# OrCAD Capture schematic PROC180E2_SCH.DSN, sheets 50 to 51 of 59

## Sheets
50 20. CPLD CLOCK GENERATION: size C; title: CPLD CLOCK GENERATION
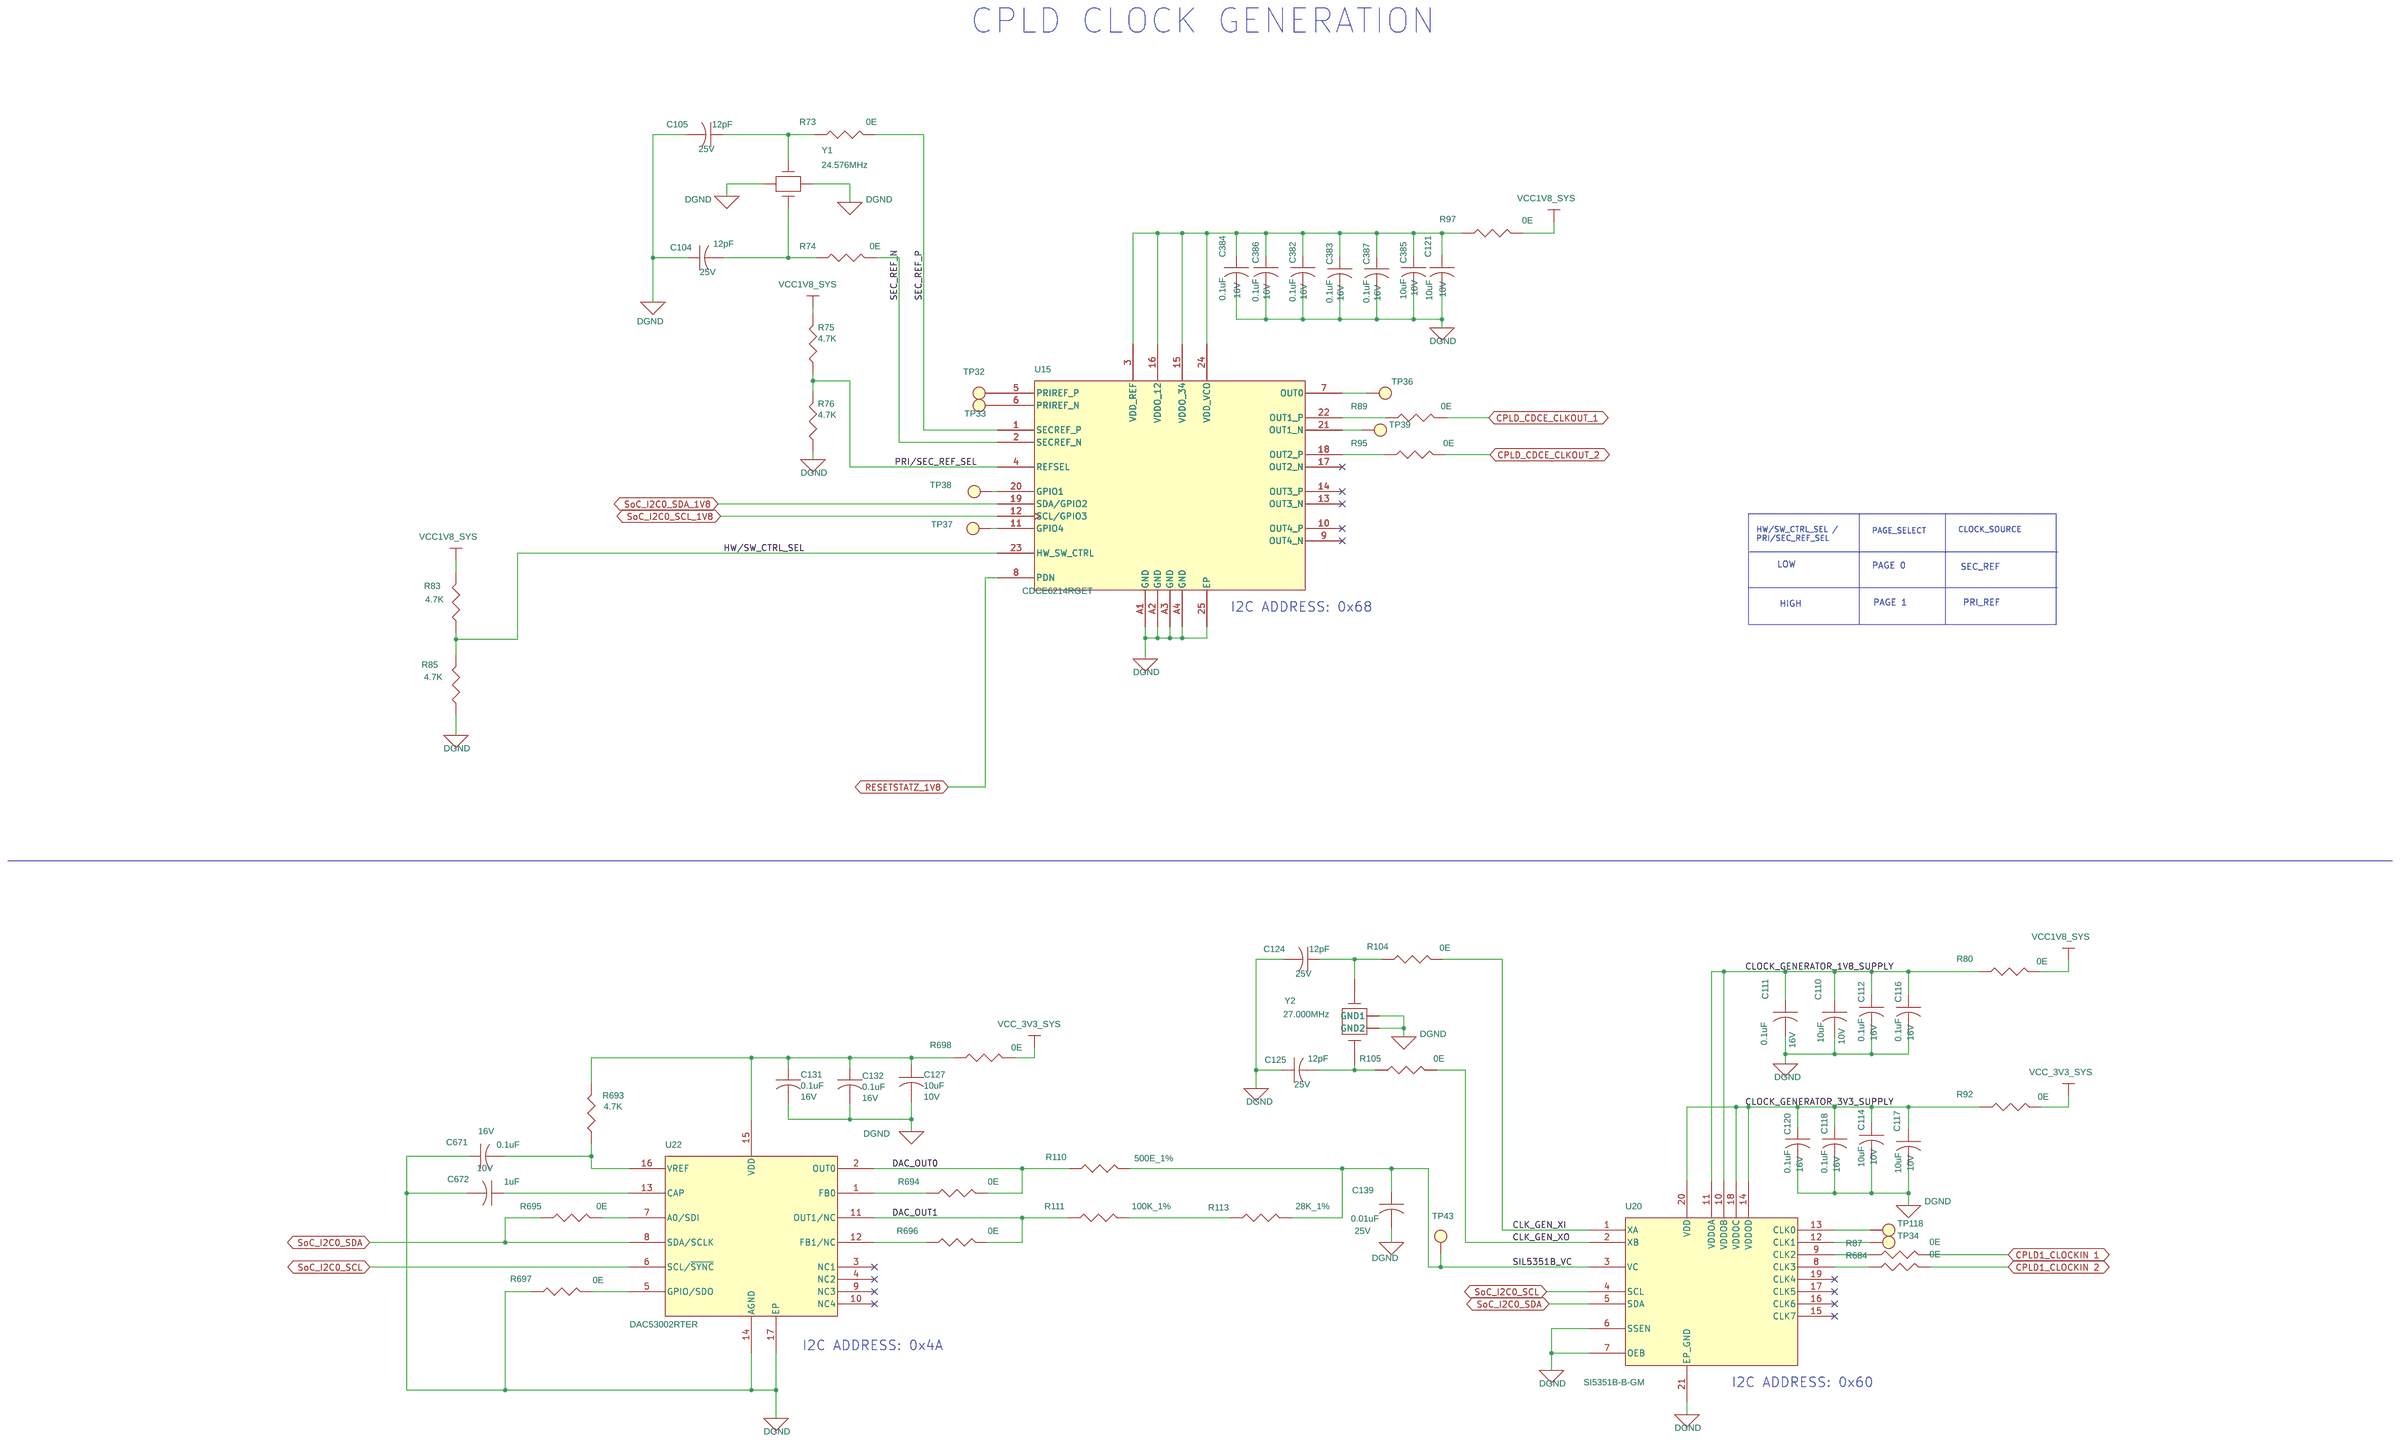
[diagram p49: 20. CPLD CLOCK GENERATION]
51 35. USB1 TYPE-A: size C; title: USB1 TYPE-A
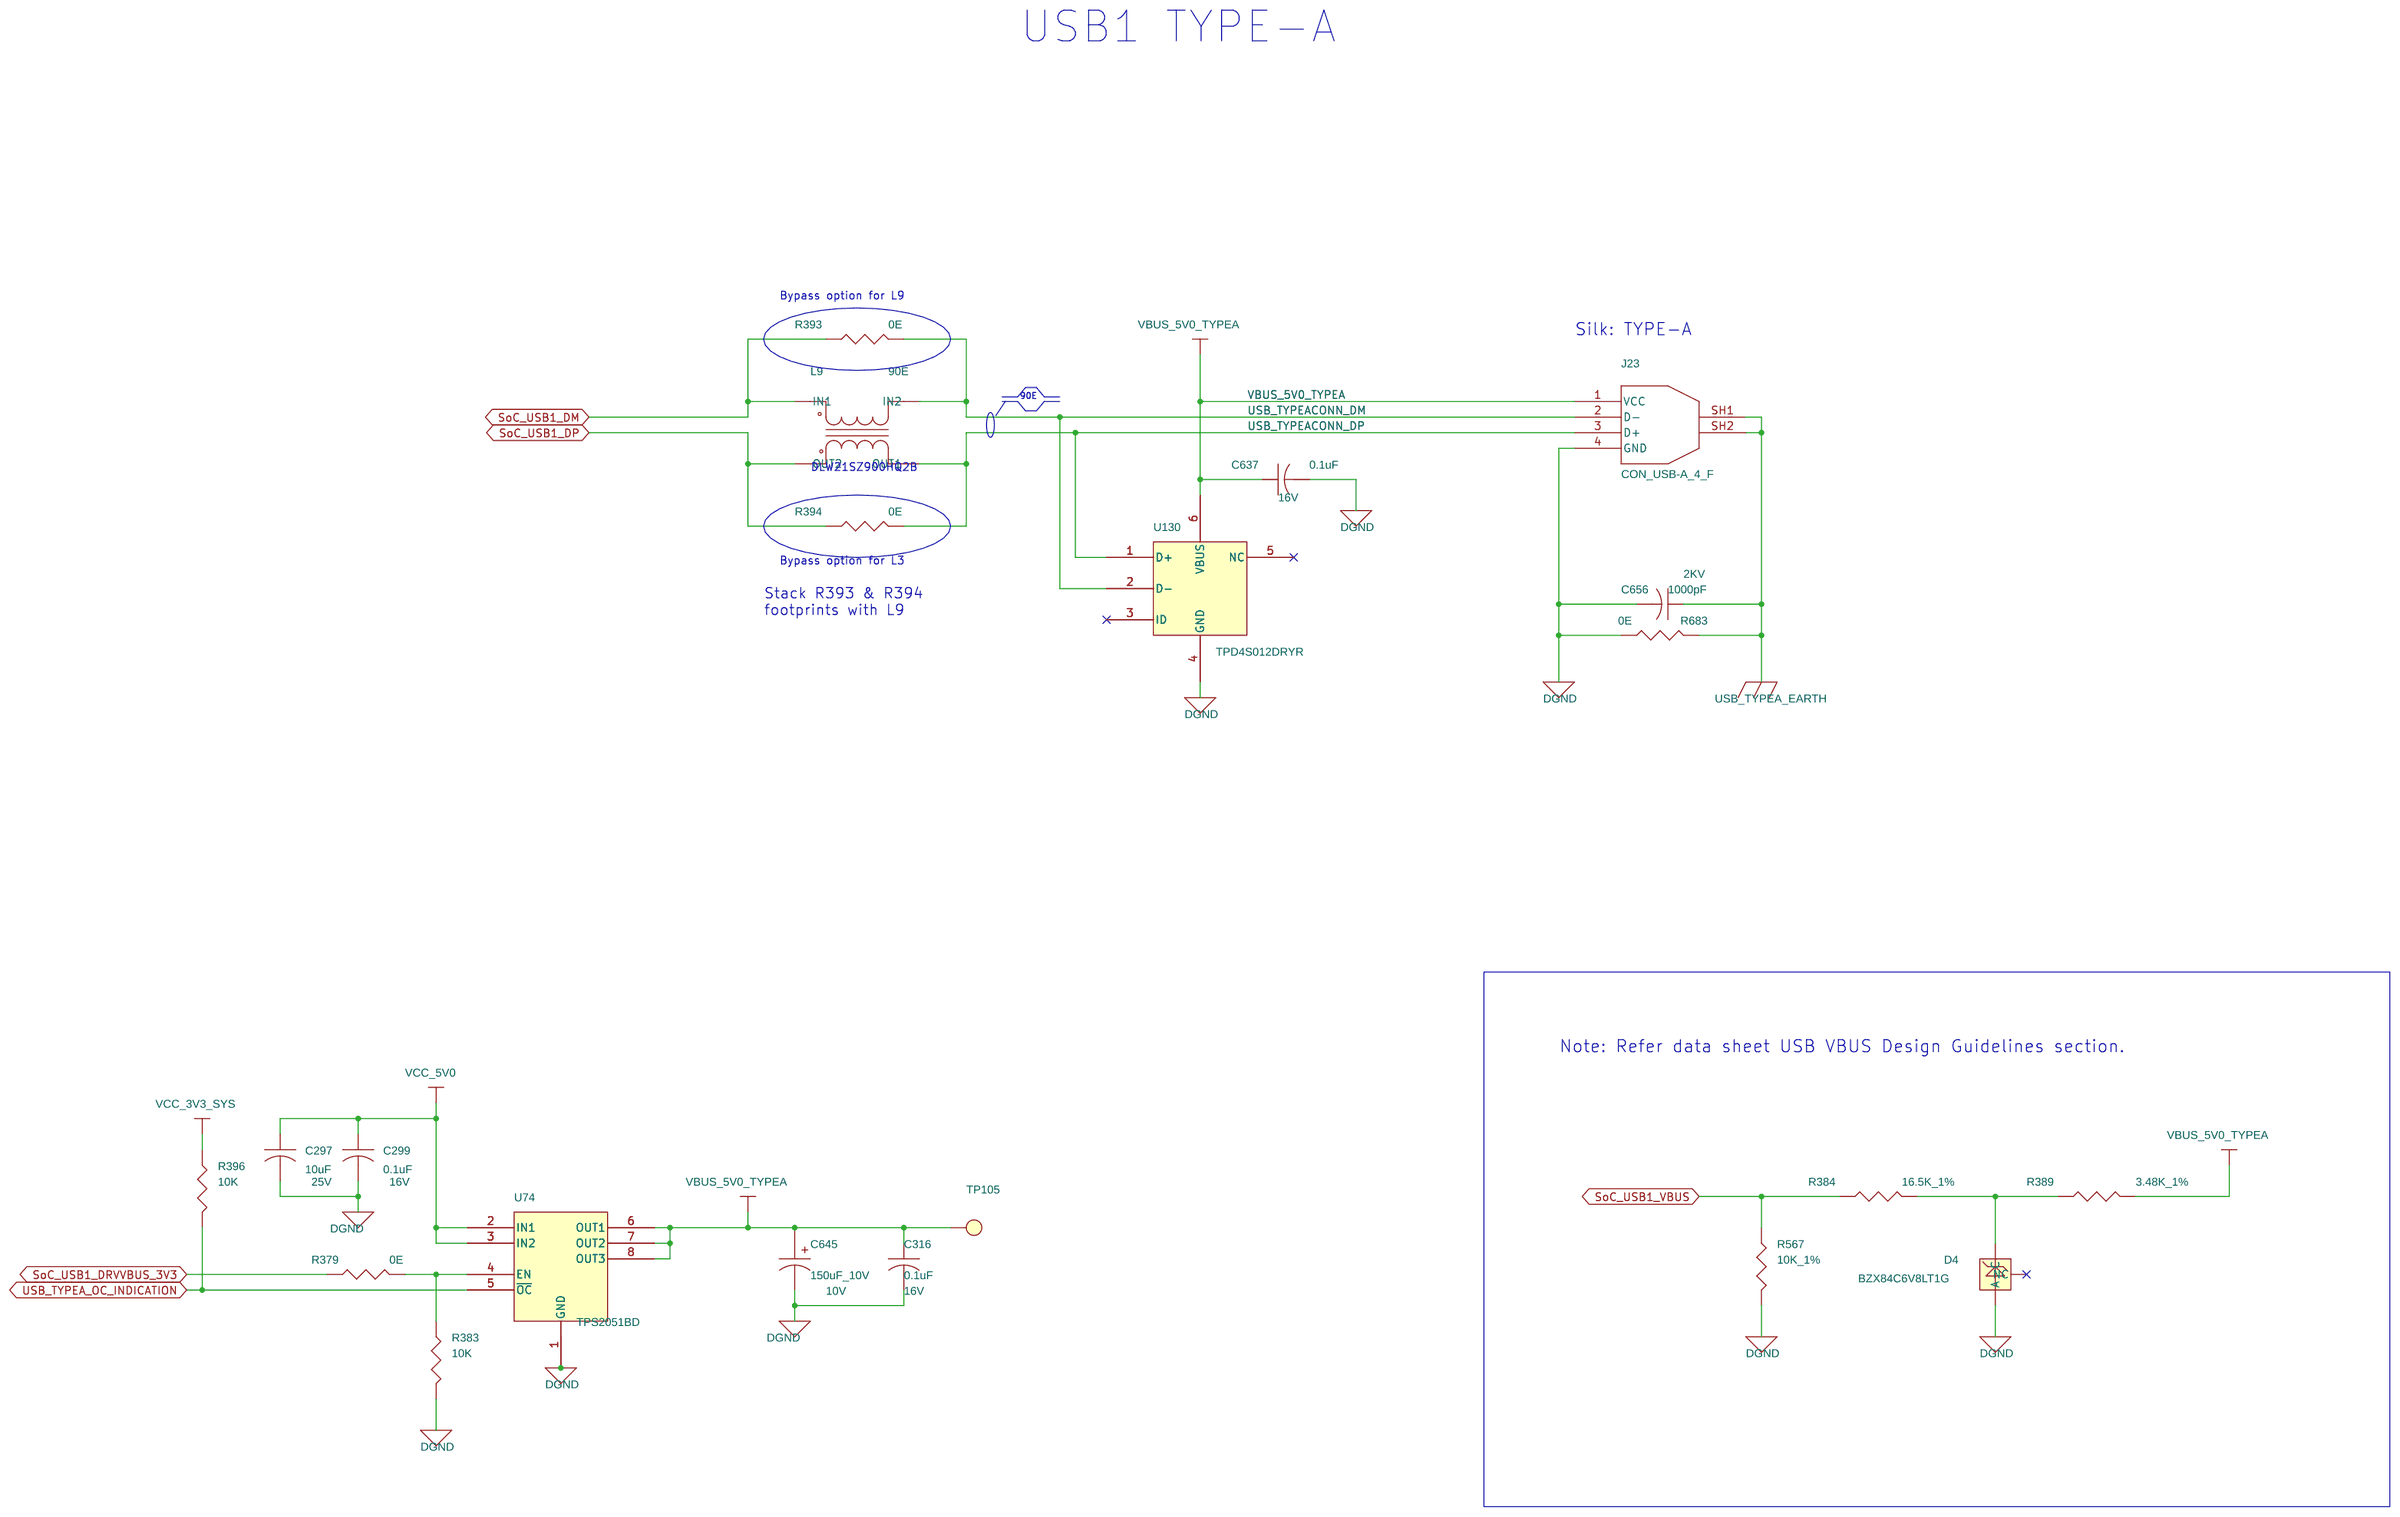
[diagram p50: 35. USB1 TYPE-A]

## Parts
sheet 20. CPLD CLOCK GENERATION
C104  12pF  [CAP0201_0-5]
C105  12pF  [CAP0201_0-5]
C110  10uF  [CAP0402_0-75]
C111  0.1uF  [CAP0201_0-5]
C112  0.1uF  [CAP0201_0-5]
C114  10uF  [CAP0402_0-75]
C116  0.1uF  [CAP0201_0-5]
C117  10uF  [CAP0402_0-75]
C118  0.1uF  [CAP0201_0-5]
C120  0.1uF  [CAP0201_0-5]
C121  10uF  [CAP0402_0-75]
C124  12pF  [CAP0201_0-5]
C125  12pF  [CAP0201_0-5]
C127  10uF  [CAP0402_0-75]
C131  0.1uF  [CAP0201_0-5]
C132  0.1uF  [CAP0201_0-5]
C139  0.01uF  [CAP0201_0-5]
C382  0.1uF  [CAP0201_0-5]
C383  0.1uF  [CAP0201_0-5]
C384  0.1uF  [CAP0201_0-5]
C385  10uF  [CAP0402_0-75]
C386  0.1uF  [CAP0201_0-5]
C387  0.1uF  [CAP0201_0-5]
C671  0.1uF  [CAP0201_0-5]
C672  1uF  [CAP0201_0-5]
R73  0E  [RES0201_0-5]
R74  0E  [RES0201_0-5]
R75  4.7K  [RES0201_0-5]
R76  4.7K  [RES0201_0-5]
R80  0E  [RES0603_0-75]
R83  4.7K  [RES0201_0-5]
R85  4.7K  [RES0201_0-5]
R87  0E  [RES0201_0-5]
R89  0E  [RES0201_0-5]
R92  0E  [RES0603_0-75]
R95  0E  [RES0201_0-5]
R97  0E  [RES0603_0-75]
R104  0E  [RES0201_0-5]
R105  0E  [RES0201_0-5]
R110  500E_1%  [RES0402_0-5]
R111  100K_1%  [RES0402_0-5]
R113  28K_1%  [RES0402_0-5]
R684  0E  [RES0201_0-5]
R693  4.7K  [RES0201_0-5]
R694  0E  [RES0201_0-5]
R695  0E  [RES0201_0-5]
R696  0E  [RES0201_0-5]
R697  0E  [RES0201_0-5]
R698  0E  [RES0603_0-75]
TP32  TP30_SMD  [TP30_SMD]
TP33  TP30_SMD  [TP30_SMD]
TP34  TP30_SMD  [TP30_SMD]
TP36  TP30_SMD  [TP30_SMD]
TP37  TP30_SMD  [TP30_SMD]
TP38  TP30_SMD  [TP30_SMD]
TP39  TP30_SMD  [TP30_SMD]
TP43  TP30_SMD  [TP30_SMD]
TP118  TP30_SMD  [TP30_SMD]
U15  CDCE6214RGET  [WFQFN24_CDCE6214-Q1_160X160_0-9]
U20  SI5351B-B-GM  [QFN20_19-68_160X160_0-9_EP2-7]
U22  DAC53002RTER  [WQFN16_19-68_120X120_0-8_EP1-7]
Y1  24.576MHz  [XTAL4_ABMM_280X200_SMD_1-3]
Y2  27.000MHz  [XTAL4_ABM8_130X110_0-8_SMD]
sheet 35. USB1 TYPE-A
C297  10uF  [CAP0603_1]
C299  0.1uF  [CAP0201_0-5]
C316  0.1uF  [CAP0201_0-5]
C637  0.1uF  [CAP0201_0-5]
C645  150uF_10V  [CAPT7343D_3-25]
C656  1000pF  [CAP1206_1-75]
D4  BZX84C6V8LT1G  [SOT23-123_1-2]
J23  CON_USB-A_4_F  [CON_USBA4_629104151_S_R_S_7-4]
L9  90E  [IND4_DLW21H_90X60_SMD_1-4]
R379  0E  [RES0201_0-5]
R383  10K  [RES0201_0-5]
R384  16.5K_1%  [RES0402_0-5]
R389  3.48K_1%  [RES0201_0-5]
R393  0E  [RES0402_0-5]
R394  0E  [RES0402_0-5]
R396  10K  [RES0201_0-5]
R567  10K_1%  [RES0201_0-5]
R683  0E  [RES0603_0-75]
TP105  TP20_SMD  [TP20_SMD]
U74  TPS2051BD  [SOIC8_1-8]
U130  TPD4S012DRYR  [SON6_SN74LVC2G17_40X60_0-6]

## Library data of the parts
C104 C105 C124 C125 = CAP: CAP CERAMIC 12pF 25V 5% C0G(NP0) AUTO 0201; Chkd/date: MANIRAJA/311221; Crtd /date: ALVY/301221; Custom_Duty: 15%; Customs_HS_Code: 85322990; Distributor_name: MOUSER; Distributor_part_number: 81-GRT0335C1E120JA2D; Footprint Path: Y:\MIS_DATABASE\Library\ALTIUM_TOOL\PCB_FOOTPRINTS\Altium_Footprint_Lib.PcbLib; Height: 0.33MM; Library Path: Y:\MIS_DATABASE\Library\ALTIUM_TOOL\SCHEMATICS_PARTS\MS_DISCRETE_Library.schlib; Mfr_name: MURATA; Mfr_part_number: GRT0335C1E120JA02D; Mistral Part No: 120021120012-R; Package: 0201; Part_type: CAPACITORS\CERAMIC; Project: AM62Q_SKEVM_BRD; RoHS: RoHS; Temperature: -55°C+125°C; Tolerance: 5%; Voltage: 25V; Wattage: NA; Weight: 0.33mg; Datasheet: Y:\MIS_DATABASE\DATASHEETS\CAPACITORS\GRT0335C1E120JA02.PDF
C110 C114 C117 C121 C127 C385 = CAP: CAP CERAMIC 10uF 10V 20% X5R 0402; Chkd/date: PRADEEP/130623; Crtd /date: PRADEEP/130623; Custom_Duty: 15%; Customs_HS_Code: 85322990; Distributor_name: NA; Distributor_part_number: NA; Footprint Path: Y:\MIS_DATABASE\Library\ALTIUM_TOOL\PCB_FOOTPRINTS\Altium_Footprint_Lib.PcbLib; Height: 0.55MM; Library Path: Y:\MIS_DATABASE\Library\ALTIUM_TOOL\SCHEMATICS_PARTS\MS_DISCRETE_Library.schlib; Mfr_name: MURATA; Mfr_part_number: GRM155R61A106ME18; Mistral Part No: 120022060018-R; Package: 0402; Part_type: CAPACITORS\CERAMIC; Project: AM62P_SK; RoHS: RoHS; Temperature: -55°C+85°C; Tolerance: 20%; Voltage: 10V; Wattage: NA; Weight: 6mg; Datasheet: Y:\MIS_DATABASE\DATASHEETS\CAPACITORS\MURATA-GXX-SER_NOV17.PDF
C111 C112 C116 C118 C120 C131 C132 C299 C316 C382-C384 C386 C387 C637 C671 = CAP: CAP CERAMIC 0.1uF 16V 10% X7S AUTO 0201; Chkd/date: MANIRAJA/110321; Crtd /date: ALVY/110321; Custom_Duty: 15%; Customs_HS_Code: 85322990; Distributor_name: DIGIKEY; Distributor_part_number: 490-GRT033C71C104KE01DTR-ND; Footprint Path: Y:\MIS_DATABASE\Library\ALTIUM_TOOL\PCB_FOOTPRINTS\Altium_Footprint_Lib.PcbLib; Height: 0.33MM; Library Path: Y:\MIS_DATABASE\Library\ALTIUM_TOOL\SCHEMATICS_PARTS\MS_DISCRETE_Library.schlib; Mfr_name: MURATA; Mfr_part_number: GRT033C71C104KE01D; Mistral Part No: 120021030007-R; Package: 0201; Part_type: CAPACITORS\CERAMIC; Project: J7ES_SK_BRD; RoHS: RoHS; Temperature: -55°C+125°C; Tolerance: 10%; Voltage: 16V; Wattage: NA; Weight: 330mg; Datasheet: Y:\MIS_DATABASE\DATASHEETS\CAPACITORS\GRT033C71C104KE01.PDF
C139 = CAP: CAP CERAMIC 0.01uF 25V 10% X5R AUTO 0201; Chkd/date: MANIRAJA/311221; Crtd /date: ALVY/301221; Custom_Duty: 15%; Customs_HS_Code: 85322990; Distributor_name: MOUSER; Distributor_part_number: 81-GRT033R61E103KE1D; Footprint Path: Y:\MIS_DATABASE\Library\ALTIUM_TOOL\PCB_FOOTPRINTS\Altium_Footprint_Lib.PcbLib; Height: 0.33MM; Library Path: Y:\MIS_DATABASE\Library\ALTIUM_TOOL\SCHEMATICS_PARTS\MS_DISCRETE_Library.schlib; Mfr_name: MURATA; Mfr_part_number: GRT033R61E103KE01D; Mistral Part No: 120021120019-R; Package: 0201; Part_type: CAPACITORS\CERAMIC; Project: AM62Q_SKEVM_BRD; RoHS: RoHS; Temperature: -55°C+85°C; Tolerance: 10%; Voltage: 25V; Wattage: NA; Weight: 0.33mg; Datasheet: Y:\MIS_DATABASE\DATASHEETS\CAPACITORS\GRT033R61E103KE01.PDF
C672 = CAP: CAP CERAMIC 1uF 10V 20% X6S 0201; Chkd/date: PRADEEP/130623; Crtd /date: PRADEEP/130623; Custom_Duty: 15%; Customs_HS_Code: 85322990; Distributor_name: DIGIKEY; Distributor_part_number: 490-GRT033C81A105ME13DTR-ND; Footprint Path: Y:\MIS_DATABASE\Library\ALTIUM_TOOL\PCB_FOOTPRINTS\Altium_Footprint_Lib.PcbLib; Height: 0.39MM; Library Path: Y:\MIS_DATABASE\Library\ALTIUM_TOOL\SCHEMATICS_PARTS\MS_DISCRETE_Library.schlib; Mfr_name: MURATA; Mfr_part_number: GRT033C81A105ME13D; Mistral Part No: 120022060020-R; Package: 0201; Part_type: CAPACITORS\CERAMIC; Project: AM62P_SK; RoHS: RoHS; Temperature: -55°C+105°C; Tolerance: 20%; Voltage: 10V; Wattage: NA; Weight: NA; Datasheet: Y:\MIS_DATABASE\DATASHEETS\CAPACITORS\GRT033C81A105ME13D.PDF
R73 R74 R87 R89 R95 R104 R105 R684 = RESISTOR: RES 0E 1/20W 5% 0201; Chkd/date: NAVEED/301214; Crtd /date: MUDDU/120710; Custom_Duty: 15%; Customs_HS_Code: 85332119; Distributor_name: DIGIKEY; Distributor_part_number: 311-0.0NCT-ND; Footprint Path: Y:\MIS_DATABASE\Library\ALTIUM_TOOL\PCB_FOOTPRINTS\Altium_Footprint_Lib.PcbLib; Height: 0.26MM; Library Path: Y:\MIS_DATABASE\Library\ALTIUM_TOOL\SCHEMATICS_PARTS\MS_DISCRETE_Library.schlib; Mfr_name: YAGEO AMERICA; Mfr_part_number: RC0201JR-070RL; Mistral Part No: 110010070067-R; Package: 0201; Part_type: RESISTORS\FIXED; Project: PB_BUGBASE; RoHS: RoHS; SIGNAL_MODEL: RESISTOR_RES0201_0-5_22E_1%_22E_1%; Temperature: -55°C+125°C; Tolerance: 5%; Voltage: NA; Wattage: 1/20W; Weight: 0.17mg; Datasheet: Y:\MIS_DATABASE\DATASHEETS\RESISTORS\RCXXXXL-SER_MAR18.PDF
R75 R76 R83 R85 R693 = RESISTOR: RES 4.7K 1/20W 5% 0201; Chkd/date: MANIRAJA/200921; Crtd /date: ALVY/200921; Custom_Duty: 15%; Customs_HS_Code: 85332119; Distributor_name: DIGIKEY; Distributor_part_number: 311-4.7KNCT-ND; Footprint Path: Y:\MIS_DATABASE\Library\ALTIUM_TOOL\PCB_FOOTPRINTS\Altium_Footprint_Lib.PcbLib; Height: 0.26MM; Library Path: Y:\MIS_DATABASE\Library\ALTIUM_TOOL\SCHEMATICS_PARTS\MS_DISCRETE_Library.schlib; Mfr_name: YAGEO AMERICA; Mfr_part_number: RC0201JR-074K7L; Mistral Part No: 110021090007-R; Package: 0201; Part_type: RESISTORS\FIXED; Project: TI_AM62x SKEVM_BRD; RoHS: RoHS; Temperature: -55°C+125°C; Tolerance: 5%; Voltage: NA; Wattage: 1/20W; Weight: 0.17mg; Datasheet: Y:\MIS_DATABASE\DATASHEETS\RESISTORS\RCXXXXL-SER_MAR18.PDF
R80 R92 R97 R698 = RESISTOR: RES 0E 1/10W 5% 0603; Chkd/date: MANIRAJA/051217; Crtd /date: BAVISH/180211; Custom_Duty: 15%; Customs_HS_Code: 85332119; Distributor_name: DIGIKEY; Distributor_part_number: 311-0.0GRCT-ND; Footprint Path: Y:\MIS_DATABASE\Library\ALTIUM_TOOL\PCB_FOOTPRINTS\Altium_Footprint_Lib.PcbLib; Height: 0.55MM; Library Path: Y:\MIS_DATABASE\Library\ALTIUM_TOOL\SCHEMATICS_PARTS\MS_DISCRETE_Library.schlib; Mfr_name: YAGEO AMERICA; Mfr_part_number: RC0603JR-070RL; Mistral Part No: 110011020013-R; Package: 0603; Part_type: RESISTORS\FIXED; Project: KENNEL; RoHS: RoHS; Temperature: -55°C+155°C; Tolerance: 5%; Voltage: NA; Wattage: 1/10W; Weight: 2mg; Datasheet: Y:\MIS_DATABASE\DATASHEETS\RESISTORS\RCXXXXL-SER_MAR18.PDF
R110 = RESISTOR: RES 500E 1/16W 1% 0402; Crtd /date: TAMILARASU/080224; Custom_Duty: 15%; Customs_HS_Code: 85332119; Distributor_name: DIGIKEY; Distributor_part_number: 13-RT0402FRE07500RLCT-ND; Footprint Path: Y:\MIS_DATABASE\Library\ALTIUM_TOOL\PCB_FOOTPRINTS\Altium_Footprint_Lib.PcbLib; Height: 0.35MM; Library Path: Y:\MIS_DATABASE\Library\ALTIUM_TOOL\SCHEMATICS_PARTS\MS_DISCRETE_Library.schlib; Mfr_name: YAGEO AMERICA; Mfr_part_number: RT0402FRE07500RL; Mistral Part No: 110024020024-R; Package: 0402; Part_type: RESISTORS\FIXED; Project: AM62D_EVM; RoHS: RoHS; Temperature: -55°C+155°C; Tolerance: 1%; Voltage: NA; Wattage: 1/16W; Weight: 0.65mg; Datasheet: Y:\MIS_DATABASE\DATASHEETS\RESISTORS\YAGEO_RT-SERIES.PDF
R111 = RESISTOR: RES 100K 1/10W 1% 0402; Chkd/date: VASANTHA/201216; Crtd /date: MAZHAR/130306; Custom_Duty: 15%; Customs_HS_Code: 85332119; Distributor_name: DIGIKEY; Distributor_part_number: P100KLCT-ND; Footprint Path: Y:\MIS_DATABASE\Library\ALTIUM_TOOL\PCB_FOOTPRINTS\Altium_Footprint_Lib.PcbLib; Height: 0.40MM; Library Path: Y:\MIS_DATABASE\Library\ALTIUM_TOOL\SCHEMATICS_PARTS\MS_DISCRETE_Library.schlib; Mfr_name: PANASONIC-ECG; Mfr_part_number: ERJ-2RKF1003X; Mistral Part No: 110009030187-R; Package: 0402; Part_type: RESISTORS\FIXED; Project: J32; RoHS: RoHS; Temperature: -55°C+155°C; Tolerance: 1%; Voltage: NA; Wattage: 1/10W; Weight: 0.8mg; Datasheet: Y:\MIS_DATABASE\DATASHEETS\RESISTORS\PAN-ERJSER_NOV17.PDF
R113 = RESISTOR: RES 28K 1/10W 1% 0402; Chkd/date: MAZHAR/250809; Crtd /date: USMAN/120809; Custom_Duty: 15%; Customs_HS_Code: 85332119; Distributor_name: DIGIKEY; Distributor_part_number: P28.0KLCT-ND; Footprint Path: Y:\MIS_DATABASE\Library\ALTIUM_TOOL\PCB_FOOTPRINTS\Altium_Footprint_Lib.PcbLib; Height: 0.40MM; Library Path: Y:\MIS_DATABASE\Library\ALTIUM_TOOL\SCHEMATICS_PARTS\MS_DISCRETE_Library.schlib; Mfr_name: PANASONIC-ECG; Mfr_part_number: ERJ-2RKF2802X; Mistral Part No: 110009080014-R; Package: 0402; Part_type: RESISTORS\FIXED; Project: VMEFMCD; RoHS: RoHS; Temperature: -55°C+155°C; Tolerance: 1%; Voltage: NA; Wattage: 1/10W; Weight: 0.8mg; Datasheet: Y:\MIS_DATABASE\DATASHEETS\RESISTORS\PAN-ERJSER_NOV17.PDF
R379 R694-R697 = RESISTOR: RES 0E 1/20W 5% 0201; Chkd/date: NAVEED/301214; Crtd /date: MUDDU/120710; Custom_Duty: 15%; Customs_HS_Code: 85332119; Distributor_name: DIGIKEY; Distributor_part_number: 311-0.0NCT-ND; Footprint Path: Y:\MIS_DATABASE\Library\ALTIUM_TOOL\PCB_FOOTPRINTS\Altium_Footprint_Lib.PcbLib; Height: 0.26MM; Library Path: Y:\MIS_DATABASE\Library\ALTIUM_TOOL\SCHEMATICS_PARTS\MS_DISCRETE_Library.schlib; Mfr_name: YAGEO AMERICA; Mfr_part_number: RC0201JR-070RL; Mistral Part No: 110010070067-R; Package: 0201; Part_type: RESISTORS\FIXED; Project: PB_BUGBASE; RoHS: RoHS; Temperature: -55°C+125°C; Tolerance: 5%; Voltage: NA; Wattage: 1/20W; Weight: 0.17mg; Datasheet: Y:\MIS_DATABASE\DATASHEETS\RESISTORS\RCXXXXL-SER_MAR18.PDF
TP32-TP34 TP36-TP39 TP43 TP118 = TESTPOINT: TESTPOINT CIR 30 SMD; Chkd/date: SHREESHAIL/171006; Crtd /date: MAZHAR/171006; Custom_Duty: NA; Customs_HS_Code: NA; Distributor_name: NA; Distributor_part_number: NA; Footprint Path: Y:\MIS_DATABASE\Library\ALTIUM_TOOL\PCB_FOOTPRINTS\Altium_Footprint_Lib.PcbLib; Height: NA; Library Path: Y:\MIS_DATABASE\Library\ALTIUM_TOOL\SCHEMATICS_PARTS\MS_DISCRETE_Library.schlib; MECHANICAL 3D STEP FILE: NA; Mfr_name: LOCAL; Mistral Part No: 130009030930; Package: SMD; Project: BT MODULE_CSRBC04; RoHS: NA; Temperature: NA; Tolerance: NA; Voltage: NA; Wattage: NA; Weight: NA; Datasheet: NA
U15 = CDCE6214_WFQFN24: IC CLOCK GENERATOR WITH 1-PLL 4-DIFFERENTIAL O/Ps 2-I/Ps AND EEPROM WFQFN24; Chkd/date: PRADEEP/290124; Crtd /date: TAMILARASU/290124; Custom_Duty: 15%; Customs_HS_Code: 85423100; Distributor_name: DIGIKEY; Distributor_part_number: 296-CDCE6214RGETCT-ND; Footprint Path: Y:\MIS_DATABASE\Library\ALTIUM_TOOL\PCB_FOOTPRINTS\Altium_Footprint_Lib.PcbLib; Height: 0.90MM; Library Path: Y:\MIS_DATABASE\Library\ALTIUM_TOOL\SCHEMATICS_PARTS\MS_COMBINATIONAL_Library.schlib; Mfr_name: TEXAS INSTRUMENTS; Mistral Part No: 141024010005-R; Package: WFQFN24; Part_type: ICS\DIGITAL\PERIPHERAL; Project: AM62D EVM; RoHS: RoHS; Temperature: -40°C+85°C; Tolerance: NA; Voltage: NA; Wattage: NA; Weight: NA; Datasheet: Y:\MIS_DATABASE\DATASHEETS\ICS\DIGITAL\PERIPHERAL\CDCE6214.PDF
U20 = SI5351B_QFN20: IC I2C-PROGRAMMABLE ANY-FREQUENCY CMOS CLOCK GENERATOR +VCXO QFN20; Chkd/date: PRADEEP/020224; Crtd /date: TAMILARASU010224; Custom_Duty: 15%; Customs_HS_Code: 85423100; Distributor_name: DIGIKEY; Distributor_part_number: 336-2401-ND; Footprint Path: Y:\MIS_DATABASE\Library\ALTIUM_TOOL\PCB_FOOTPRINTS\Altium_Footprint_Lib.PcbLib; Height: 0.90MM; Library Path: Y:\MIS_DATABASE\Library\ALTIUM_TOOL\SCHEMATICS_PARTS\MS_COMBINATIONAL_Library.schlib; Mfr_name: SKYWORKS SOLUTIONS INC; Mistral Part No: 141024020002-R; Package: QFN20; Part_type: ICS\DIGITAL\PERIPHERAL; Project: AM62D EVM; RoHS: RoHS; Temperature: -40°C+85°C; Tolerance: NA; Voltage: NA; Wattage: NA; Weight: NA; Datasheet: Y:\MIS_DATABASE\DATASHEETS\ICS\DIGITAL\PERIPHERAL\SI5351X-B.PDF
U22 = DAC53002_WQFN16: IC 12-BIT AND 10-BIT ULTRA-LOW POWER DUAL AND SINGLE VOLTAGE AND CURRENT OUTPUT SMART DACS WQFN16; Crtd /date: SHANKARI/060924; Custom_Duty: 15%; Customs_HS_Code: 85423100; Distributor_name: DIGIKEY; Distributor_part_number: 296-DAC53002RTERCT-ND; Footprint Path: Y:\MIS_DATABASE\Library\ALTIUM_TOOL\PCB_FOOTPRINTS\Altium_Footprint_Lib.PcbLib; Height: 0.80MM; Library Path: Y:\MIS_DATABASE\Library\ALTIUM_TOOL\SCHEMATICS_PARTS\MS_ATOD_Library.schlib; Mfr_name: TEXAS INSTRUMENTS; Mistral Part No: 140224090001-R; Package: WQFN16; Part_type: ICS\DTOA; Project: AM62D_EVM; RoHS: RoHS; Temperature: -40°C+125°C; Tolerance: NA; Voltage: NA; Wattage: NA; Weight: NA; Datasheet: Y:\MIS_DATABASE\DATASHEETS\ICS\ATOD_DTOA\DAC53002RTER.PDF
Y1 = CRY4_ABMM: CRY 24.576MHz 18pF SMD; Chkd/date: MANIRAJA/040918; Crtd /date: GEETHA/040506; Custom_Duty: 24%; Customs_HS_Code: 85439000; Distributor_name: DIGIKEY; Distributor_part_number: 535-9160-1-ND; Footprint Path: Y:\MIS_DATABASE\Library\ALTIUM_TOOL\PCB_FOOTPRINTS\Altium_Footprint_Lib.PcbLib; Height: 1.30MM; Library Path: Y:\MIS_DATABASE\Library\ALTIUM_TOOL\SCHEMATICS_PARTS\MS_DISCRETE_Library.schlib; Mfr_name: ABRACON; Mfr_part_number: ABMM-24.576MHZ-B2-T; Mistral Part No: 130009030042-R; Package: SMD; Part_type: CRYSTAL; Project: SCRIPTALKMAX; RoHS: RoHS; Temperature: -20°C+70°C; Tolerance: NA; Voltage: NA; Wattage: NA; Weight: 186.03mg; Datasheet: Y:\MIS_DATABASE\DATASHEETS\MISC\CRY_OSC\ABMM-SERIES.PDF
Y2 = CRY4_ABM8: CRY 27.000MHz SMD; Chkd/date: PRADEEP/020224; Crtd /date: TAMILARASU/020224; Custom_Duty: 24%; Customs_HS_Code: 85437099; Distributor_name: DIGIKEY; Distributor_part_number: 535-9679-1-ND; Height: 0.80MM; Mfr_name: ABRACON; Mfr_part_number: ABM8-27.000MHZ-10-1-U-T; Mistral Part No: 130024020001-R; Package: SMD; Part_type: CRYSTAL; Project: AM62D EVM; RoHS: RoHS; Temperature: -10°C+60°C; Tolerance: NA; Voltage: NA; Wattage: NA; Weight: NA; Datasheet: Y:\MIS_DATABASE\DATASHEETS\MISC\CRY_OSC\ABM8-27.000MHZ-10-1-U-T.PDF
C297 = CAP: CAP CERAMIC 10uF 25V 20% X5R AUTO 0603; Chkd/date: PRADEEP/130623; Crtd /date: PRADEEP/130623; Custom_Duty: 15%; Customs_HS_Code: 85322990; Distributor_name: NA; Distributor_part_number: NA; Footprint Path: Y:\MIS_DATABASE\Library\ALTIUM_TOOL\PCB_FOOTPRINTS\Altium_Footprint_Lib.PcbLib; Height: 1.00MM; Library Path: Y:\MIS_DATABASE\Library\ALTIUM_TOOL\SCHEMATICS_PARTS\MS_DISCRETE_Library.schlib; Mfr_name: MURATA; Mfr_part_number: GRT188R61E106ME13; Mistral Part No: 120022060023-R; Package: 0603; Part_type: CAPACITORS\CERAMIC; Project: AM62P_SK; RoHS: RoHS; Temperature: -55°C+85°C; Tolerance: 20%; Voltage: 25V; Wattage: NA; Weight: 2mg; Datasheet: Y:\MIS_DATABASE\DATASHEETS\CAPACITORS\GRT188R61E106ME13.PDF
C645 = CAP_POL: CAP TANTALUM 150uF 10V 10% ESR 600mE D7343; Chkd/date: ALVY/200921; Crtd /date: MANIRAJA/200921; Custom_Duty: 15%; Customs_HS_Code: 85322990; Distributor_name: DIGIKEY; Distributor_part_number: 718-1960-1-ND; Footprint Path: Y:\MIS_DATABASE\Library\ALTIUM_TOOL\PCB_FOOTPRINTS\Altium_Footprint_Lib.PcbLib; Height: 3.10MM; Library Path: Y:\MIS_DATABASE\Library\ALTIUM_TOOL\SCHEMATICS_PARTS\MS_DISCRETE_Library.schlib; Mfr_name: VISHAY; Mfr_part_number: 293D157X9010D2TE3; Mistral Part No: 120021090007-R; Package: D7343; Part_type: CAPACITORS\TANTALUM; Project: TI_AM62x SKEVM_BRD; RoHS: RoHS; Temperature: -55°C+125°C; Tolerance: 10%; Voltage: 10V; Wattage: NA; Weight: 400mg; Datasheet: Y:\MIS_DATABASE\DATASHEETS\CAPACITORS\293D_SER_MAR20.PDF
C656 = CAP: CAP CERAMIC 1000pF 2KV 10% X7R 1206; Chkd/date: SHREESHAIL/291106; Crtd /date: MAZHAR/281106; Custom_Duty: 15%; Customs_HS_Code: 85322990; Distributor_name: DIGIKEY; Distributor_part_number: 478-2956-1-ND; Footprint Path: Y:\MIS_DATABASE\Library\ALTIUM_TOOL\PCB_FOOTPRINTS\Altium_Footprint_Lib.PcbLib; Height: 1.52MM; Library Path: Y:\MIS_DATABASE\Library\ALTIUM_TOOL\SCHEMATICS_PARTS\MS_DISCRETE_Library.schlib; Mfr_name: AVX CORPORATION; Mfr_part_number: 1206GC102KAT1A; Mistral Part No: 120015080006-R; Package: 1206; Part_type: CAPACITORS\CERAMIC; Project: ADR1B; RoHS: RoHS; Temperature: -55°C+125°C; Tolerance: 10%; Voltage: 2KV; Wattage: NA; Weight: 16.2mg; Datasheet: Y:\MIS_DATABASE\DATASHEETS\CAPACITORS\AVX_HV-MLC.PDF
D4 = DIODE_ZENER_SOT23_13: DIODE ZENER 250mW 6.8V SOT23-123; Chkd/date: MANIRAJA/031017; Crtd /date: MANIRAJA/031017; Custom_Duty: 15%; Customs_HS_Code: 85412900; Distributor_name: DIGIKEY; Distributor_part_number: BZX84C6V8LT1GOSCT-ND; Height: 1.11MM; Mfr_name: ON SEMICONDUCTOR; Mistral Part No: 130017100002-R; Package: SOT23-123; Part_type: DIODE\ZENER; Project: TI_MAXIE_CPB; RoHS: RoHS; Temperature: -65°C+150°C; Tolerance: NA; Voltage: 6.8V; Wattage: NA; Weight: 8mg; Datasheet: Y:\MIS_DATABASE\DATASHEETS\DISCRETES\DIODES\BZX84XX.PDF
J23 = CON_USB-A_4_2SH: CON USB-A TYPE 4POS FEMALE RT SMD; Chkd/date: MANIRAJA/271017; Crtd /date: MANIRAJA/271017; Custom_Duty: 24%; Customs_HS_Code: 85369090; Distributor_name: DIGIKEY; Distributor_part_number: 732-5969-1-ND; Height: 7.35MM; Manufacturer: WURTH ELECTRONICS; Mfr_name: WURTH ELECTRONICS; Mfr_part_number: 629104151021; Mistral Part No: 150017100042-R; Package: SMD; Part_type: CONNECTOR\USB; Project: TI_SVB_MAXWELL_SPM; RoHS: RoHS; Temperature: -40°C+85°C; Tolerance: NA; Voltage: NA; Wattage: NA; Weight: NA; Datasheet: Y:\MIS_DATABASE\DATASHEETS\CONNECTORS\629104151021.PDF
L9 = INDUCTOR_DLW31S: IND COMMON MODE CHOKE 90E 280mA SMD; Chkd/date: MANIRAJA/270619; Crtd /date: MANIRAJA/270619; Custom_Duty: 24%; Customs_HS_Code: 85437099; Distributor_name: NA; Distributor_part_number: NA; Footprint Path: Y:\MIS_DATABASE\Library\ALTIUM_TOOL\PCB_FOOTPRINTS\Altium_Footprint_Lib.PcbLib; Height: 1.40MM; Library Path: Y:\MIS_DATABASE\Library\ALTIUM_TOOL\SCHEMATICS_PARTS\MS_DISCRETE_Library.schlib; Mfr_name: MURATA; Mfr_part_number: DLW21SZ900HQ2B; Mistral Part No: 130019060035-R; Package: SMD; Part_type: INDUCTOR; Project: TI_J7ES_CP; RoHS: RoHS; SIGNAL_MODEL: INDUCTOR_DLW31S_IND4_DLW21H_90X_90E; Temperature: -40°C+105°C; Tolerance: NA; Voltage: NA; Wattage: NA; Weight: 11mg; Datasheet: Y:\MIS_DATABASE\DATASHEETS\DISCRETES\INDUCTORS\DLW21SZ900HQ2B.PDF
R383 R396 = RESISTOR: RES 10K 1/20W 5% 0201; Chkd/date: MANIRAJA/050517; Crtd /date: MANIRAJA/050517; Custom_Duty: 15%; Customs_HS_Code: 85332119; Distributor_name: DIGIKEY; Distributor_part_number: 311-10KNCT-ND; Footprint Path: Y:\MIS_DATABASE\Library\ALTIUM_TOOL\PCB_FOOTPRINTS\Altium_Footprint_Lib.PcbLib; Height: 0.26MM; Library Path: Y:\MIS_DATABASE\Library\ALTIUM_TOOL\SCHEMATICS_PARTS\MS_DISCRETE_Library.schlib; Mfr_name: YAGEO AMERICA; Mfr_part_number: RC0201JR-0710KL; Mistral Part No: 110010070051-R; Package: 0201; Part_type: RESISTORS\FIXED; Project: GOLDEN-I LITE; RoHS: RoHS; Temperature: -55°C+125°C; Tolerance: 5%; Voltage: NA; Wattage: 1/20W; Weight: 0.17mg; Datasheet: Y:\MIS_DATABASE\DATASHEETS\RESISTORS\RCXXXXL-SER_MAR18.PDF
R384 = RESISTOR: RES 16.5K 1/16W 1% 0402; Chkd/date: ALVY/091220; Crtd /date: MANIRAJA/091220; Custom_Duty: 15%; Customs_HS_Code: 85332119; Distributor_name: DIGIKEY; Distributor_part_number: YAG3002CT-ND; Footprint Path: Y:\MIS_DATABASE\Library\ALTIUM_TOOL\PCB_FOOTPRINTS\Altium_Footprint_Lib.PcbLib; Height: 0.40MM; Library Path: Y:\MIS_DATABASE\Library\ALTIUM_TOOL\SCHEMATICS_PARTS\MS_DISCRETE_Library.schlib; Mfr_name: YAGEO AMERICA; Mfr_part_number: RC0402FR-0716K5L; Mistral Part No: 110020120011-R; Package: 0402; Part_type: RESISTORS\FIXED; Project: TI_AM243x LP EVM; RoHS: RoHS; Temperature: -55°C+155°C; Tolerance: 1%; Voltage: NA; Wattage: 1/16W; Weight: 0.65mg; Datasheet: Y:\MIS_DATABASE\DATASHEETS\RESISTORS\RCXXXXL-SER_MAR18.PDF
R389 = RESISTOR: RES 3.48K 1/20W 1% 0201; Chkd/date: PRADEEP/281123; Crtd /date: TAMILARASU/071123; Custom_Duty: 15%; Customs_HS_Code: 85322990; Distributor_name: DIGIKEY; Distributor_part_number: P122951CT-ND; Footprint Path: Y:\MIS_DATABASE\Library\ALTIUM_TOOL\PCB_FOOTPRINTS\Altium_Footprint_Lib.PcbLib; Height: 0.26MM; Library Path: Y:\MIS_DATABASE\Library\ALTIUM_TOOL\SCHEMATICS_PARTS\MS_DISCRETE_Library.schlib; Mfr_name: PANASONIC-ECG; Mfr_part_number: ERJ-1GNF3481C; Mistral Part No: 110023110006-R; Package: 0201; Part_type: RESISTORS\FIXED; Project: AM62P SK; RoHS: RoHS; Temperature: -55°C+125°C; Tolerance: 0.01; Voltage: NA; Wattage: 1/20W; Weight: 0.15mg; Datasheet: Y:\MIS_DATABASE\DATASHEETS\RESISTORS\PAN-ERJSER_DEC22.PDF
R393 R394 = RESISTOR: RES 0E 1/10W JUMPER 0402; Chkd/date: VASANTHA/061216; Crtd /date: NAVEED/201014; Custom_Duty: 15%; Customs_HS_Code: 85332119; Distributor_name: DIGIKEY; Distributor_part_number: P0.0JCT-ND; Footprint Path: Y:\MIS_DATABASE\Library\ALTIUM_TOOL\PCB_FOOTPRINTS\Altium_Footprint_Lib.PcbLib; Height: 0.40MM; IBISSP_MODLES: VALUE REPEATING 2 TIME; Library Path: Y:\MIS_DATABASE\Library\ALTIUM_TOOL\SCHEMATICS_PARTS\MS_DISCRETE_Library.schlib; Mfr_name: PANASONIC-ECG; Mfr_part_number: ERJ-2GE0R00X; Mistral Part No: 110018030052-R; Package: 0402; Part_type: RESISTORS\FIXED; Project: AEGIS POM; RoHS: RoHS; Temperature: -55°C+155°C; Tolerance: NA; Voltage: NA; Wattage: 1/10W; Weight: 0.8mg; Datasheet: Y:\MIS_DATABASE\DATASHEETS\RESISTORS\PAN-ERJSER_NOV17.PDF
R567 = RESISTOR: RES 10K 1/20W 1% 0201; Chkd/date: VASANTHA/270117; Crtd /date: MANIRAJA/270117; Custom_Duty: 15%; Customs_HS_Code: 85332119; Distributor_name: DIGIKEY; Distributor_part_number: 311-10.0KMCT-ND; Footprint Path: Y:\MIS_DATABASE\Library\ALTIUM_TOOL\PCB_FOOTPRINTS\Altium_Footprint_Lib.PcbLib; Height: 0.26MM; Library Path: Y:\MIS_DATABASE\Library\ALTIUM_TOOL\SCHEMATICS_PARTS\MS_DISCRETE_Library.schlib; Mfr_name: YAGEO AMERICA; Mfr_part_number: RC0201FR-0710KL; Mistral Part No: 110011040018-R; Package: 0201; Part_type: RESISTORS\FIXED; Project: GOLDEN-I LITE; RoHS: RoHS; Temperature: -55°C+125°C; Tolerance: 1%; Voltage: NA; Wattage: 1/20W; Weight: 0.17mg; Datasheet: Y:\MIS_DATABASE\DATASHEETS\RESISTORS\RCXXXXL-SER_MAR18.PDF
R683 = RESISTOR: RES 0E 1/10W 5% 0603; Chkd/date: MANIRAJA/051217; Crtd /date: BAVISH/180211; Custom_Duty: 15%; Customs_HS_Code: 85332119; Distributor_name: DIGIKEY; Distributor_part_number: 311-0.0GRCT-ND; Footprint Path: Y:\MIS_DATABASE\Library\ALTIUM_TOOL\PCB_FOOTPRINTS\Altium_Footprint_Lib.PcbLib; Height: 0.55MM; Library Path: Y:\MIS_DATABASE\Library\ALTIUM_TOOL\SCHEMATICS_PARTS\MS_DISCRETE_Library.schlib; Manufacturer: YAGEO AMERICA; Mfr_name: PANASONIC-ECG; Mfr_part_number: RC0603JR-070RL; Mistral Part No: 110011020013-R; Package: 0603; Part_type: RESISTORS\FIXED; Project: KENNEL; RoHS: RoHS; Temperature: -55°C+155°C; Tolerance: 5%; Voltage: NA; Wattage: 1/10W; Weight: 2mg; Datasheet: Y:\MIS_DATABASE\DATASHEETS\RESISTORS\RCXXXXL-SER_MAR18.PDF
TP105 = TESTPOINT: TESTPOINT CIR 20 SMD; Chkd/date: SHREESHAIL/171006; Crtd /date: MAZHAR/171006; Custom_Duty: NA; Customs_HS_Code: NA; Distributor_name: NA; Distributor_part_number: NA; Footprint Path: Y:\MIS_DATABASE\Library\ALTIUM_TOOL\PCB_FOOTPRINTS\Altium_Footprint_Lib.PcbLib; Height: NA; Library Path: Y:\MIS_DATABASE\Library\ALTIUM_TOOL\SCHEMATICS_PARTS\MS_DISCRETE_Library.schlib; MECHANICAL 3D STEP FILE: NA; Mfr_name: LOCAL; Mistral Part No: NA; Package: SMD; Project: BT MODULE_CSRBC04; RoHS: NA; Temperature: NA; Tolerance: NA; Voltage: NA; Wattage: NA; Weight: NA; Datasheet: NA
U74 = TPS2051BD_SOIC8: IC POWER DISTRIBUTION SWITCH SOIC8; Chkd/date: NAVEED/150714; Crtd /date: VASANTHA/190614; Custom_Duty: 15%; Customs_HS_Code: 85423100; Distributor_name: DIGIKEY; Distributor_part_number: 296-26911-5-ND; Footprint Path: Y:\MIS_DATABASE\Library\ALTIUM_TOOL\PCB_FOOTPRINTS\Altium_Footprint_Lib.PcbLib; Height: 1.75MM; Library Path: Y:\MIS_DATABASE\Library\ALTIUM_TOOL\SCHEMATICS_PARTS\MS_MISCPOWER_Library.schlib; Mfr_name: TEXAS INSTRUMENTS; Mistral Part No: 142014060011-R; Package: SOIC8; Part_type: ICS\POWER; Project: AEGIS_POM; RoHS: RoHS; Temperature: -40°C+125°C; Tolerance: NA; Voltage: NA; Wattage: NA; Weight: 72.6mg; Datasheet: Y:\MIS_DATABASE\DATASHEETS\MISC\REGULATORS\TPS2051BDBVR.PDF
U130 = TPD4S012DRY_SON6: IC 4CH ESD SOLUTION FOR USB-HS/USB OTG/USB CHARGER INTERFACE SON6; Chkd/date: MANIRAJA/040719; Crtd /date: BAVISH/190811; Custom_Duty: 15%; Customs_HS_Code: 85423100; Distributor_name: DIGIKEY; Distributor_part_number: 296-24244-1-ND; Footprint Path: Y:\MIS_DATABASE\Library\ALTIUM_TOOL\PCB_FOOTPRINTS\Altium_Footprint_Lib.PcbLib; Height: 0.60MM; Library Path: Y:\MIS_DATABASE\Library\ALTIUM_TOOL\SCHEMATICS_PARTS\MS_MISCINTERFACE_Library.schlib; Mfr_name: TEXAS INSTRUMENTS; Mistral Part No: 141011080022-R; Package: SON6; Part_type: ICS\INTERFACE; Project: ACRO_DM3730; RoHS: RoHS; Temperature: -40°C+85°C; Tolerance: NA; Voltage: NA; Wattage: NA; Weight: 3.2mg; Datasheet: Y:\MIS_DATABASE\DATASHEETS\ICS\INTERFACE\TPD4S012DRYR.PDF

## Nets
DGND: C104.1 C105.2 C110.2 C111.2 C112.2 C114.2 C116.2 C117.2 C118.2 C120.2 C121.2 C124.2 C125.1 C127.2 C131.2 C132.2 C139.2 C297.2 C299.2 C316.2 C382.2 C383.2 C384.2 C385.2 C386.2 C387.2 C637.2 C645.2 C656.2 C671.1 C672.2 D4.1(A) J23.4(GND) R76.2 R85.2 R383.2 R567.2 R683.2 R697.1 U15.25(EP) U15.A1(GND) U15.A2(GND) U15.A3(GND) U15.A4(GND) U20.6(SSEN) U20.7(OEB) U20.21(EP_GND) U22.14(AGND) U22.17(EP) U74.1(GND) U130.4(GND) Y1.2 Y1.4 Y2.2(GND1) Y2.4(GND2) ; also on sheet 1 2 3 4 5 6 7 8 9 10 12 13 14 16 17 18 19 20 21 22 31 32 33 34 35 36 37 38 39 40 41 42 43 44 45 46 47 48 49 52 53 54 55 56 57 58
VBUS_5V0_TYPEA: C316.1 C637.1 C645.1 J23.1(VCC) R389.2 TP105.1(TP) U74.6(OUT1) U74.7(OUT2) U74.8(OUT3) U130.6(VBUS)
VCC1V8_SYS: R75.1 R80.2 R83.1 R97.2 ; also on sheet 1 2 4 6 7 10 20 21 22 33 37 38 39 42 43 49 52 53 54 55 56 57 58
VCC_3V3_SYS: R92.2 R396.1 R698.2 ; also on sheet 1 2 3 6 10 14 17 18 19 20 22 31 33 37 38 40 41 42 45 46 48 49 52 53 54 55 56 57 58
VCC_5V0: C297.1 C299.1 U74.2(IN1) U74.3(IN2) ; also on sheet 6 14 31 32 34 52 54
CLK_GEN_XI: R104.1 U20.1(XA)
CLK_GEN_XO: R105.1 U20.2(XB)
CLOCK_GENERATOR_1V8_SUPPLY: C110.1 C111.1 C112.1 C116.1 R80.1 U20.10(VDDOB) U20.11(VDDOA)
CLOCK_GENERATOR_3V3_SUPPLY: C114.1 C117.1 C118.1 C120.1 R92.1 U20.14(VDDOD) U20.18(VDDOC) U20.20(VDD)
CPLD1_CLOCKIN 1: R87.1 ; also on sheet 22
CPLD1_CLOCKIN 2: R684.1 ; also on sheet 22
CPLD_CDCE_CLKOUT_1: R89.1 ; also on sheet 22
CPLD_CDCE_CLKOUT_2: R95.1 ; also on sheet 22
DAC_OUT0: R110.1 R694.2 U22.2(OUT0)
DAC_OUT1: R111.1 R696.2 U22.11(OUT1/NC)
HW/SW_CTRL_SEL: R83.2 R85.1 U15.23(HW_SW_CTRL)
PRI/SEC_REF_SEL: R75.2 R76.1 U15.4(REFSEL)
RESETSTATZ_1V8: U15.8(PDN) ; also on sheet 10 20 22
SEC_REF_N: R74.1 U15.2(SECREF_N)
SEC_REF_P: R73.1 U15.1(SECREF_P)
SIL5351B_VC: C139.1 R110.2 R113.2 TP43.1(TP) U20.3(VC)
SoC_I2C0_SCL: U20.4(SCL) U22.6(SCL/~{SYNC}) ; also on sheet 1 3 17 20 22 40 41 55
SoC_I2C0_SCL_1V8: U15.12(SCL/GPIO3) ; also on sheet 1 5 7 21 49 53 56
SoC_I2C0_SDA: R695.1 U20.5(SDA) U22.8(SDA/SCLK) ; also on sheet 1 3 17 20 22 40 41 55
SoC_I2C0_SDA_1V8: U15.19(SDA/GPIO2) ; also on sheet 1 5 7 21 49 53 56
SoC_USB1_DM: L9.1(IN1) R393.1 ; also on sheet 8
SoC_USB1_DP: L9.4(OUT2) R394.1 ; also on sheet 8
SoC_USB1_DRVVBUS_3V3: R379.1 ; also on sheet 52
SoC_USB1_VBUS: R384.1 R567.1 ; also on sheet 8
USB_TYPEA_EARTH: C656.1 J23.SH1 J23.SH2 R683.1
USB_TYPEA_OC_INDICATION: R396.2 U74.5(~{OC}) ; also on sheet 55
USB_TYPEACONN_DM: J23.2(D-) L9.2(IN2) R393.2 U130.2(D-)
USB_TYPEACONN_DP: J23.3(D+) L9.3(OUT1) R394.2 U130.1(D+)
N20199452: D4.3(C) R384.2 R389.1
N24582539: R379.2 R383.1 U74.4(EN)
N27175754: R95.2 U15.18(OUT2_P)
N27175817: C104.2 R74.2 Y1.1
N27175821: C105.1 R73.2 Y1.3
N27175987: C121.1 C382.1 C383.1 C384.1 C385.1 C386.1 C387.1 R97.1 U15.3(VDD_REF) U15.15(VDDO_34) U15.16(VDDO_12) U15.24(VDD_VCO)
N27176057: TP36.1(TP) U15.7(OUT0)
N27176072: R89.2 U15.22(OUT1_P)
N27176107: TP39.1(TP) U15.21(OUT1_N)
N27176638: TP37.1(TP) U15.11(GPIO4)
N27176640: TP38.1(TP) U15.20(GPIO1)
N27177989: C124.1 R104.2 Y2.1
N27177993: C125.2 R105.2 Y2.3
N27178282: TP34.1(TP) U20.12(CLK1)
N27850214: R87.2 U20.9(CLK2)
N27852984: R684.2 U20.8(CLK3)
N27853046: TP118.1(TP) U20.13(CLK0)
N27894941: C671.2 R693.2 U22.16(VREF)
N27894993: C127.1 C131.1 C132.1 R693.1 R698.1 U22.15(VDD)
N27895110: R697.2 U22.5(GPIO/SDO)
N27895165: C672.1 U22.13(CAP)
N27950234: TP32.1(TP) U15.5(PRIREF_P)
N27950235: TP33.1(TP) U15.6(PRIREF_N)
N27951059: R695.2 U22.7(A0/SDI)
N27951986: R111.2 R113.1
N27952439: R694.1 U22.1(FB0)
N27952516: R696.1 U22.12(FB1/NC)

Not connected (* = marked no-connect by the designer): D4 2(NC)*; U15 9(OUT4_N)* 10(OUT4_P)* 13(OUT3_N)* 14(OUT3_P)* 17(OUT2_N)*; U20 15(CLK7)* 16(CLK6)* 17(CLK5)* 19(CLK4)*; U22 3(NC1)* 4(NC2)* 9(NC3)* 10(NC4)*; U130 3(ID)* 5(NC)*

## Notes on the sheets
sheet 50
- CPLD CLOCK GENERATION
- HW/SW_CTRL_SEL /
  PRI/SEC_REF_SEL
- PAGE_SELECT
- CLOCK_SOURCE
- LOW
- PAGE 0
- SEC_REF
- HIGH
- PAGE 1
- PRI_REF
- I2C ADDRESS: 0x68
- I2C ADDRESS: 0x4A
- I2C ADDRESS: 0x60
sheet 51
- USB1 TYPE-A
- Bypass option for L9
- Silk: TYPE-A
- 90E
- DLW21SZ900HQ2B
- Bypass option for L3
- Stack R393 & R394
  footprints with L9
- Note: Refer data sheet USB VBUS Design Guidelines section.
